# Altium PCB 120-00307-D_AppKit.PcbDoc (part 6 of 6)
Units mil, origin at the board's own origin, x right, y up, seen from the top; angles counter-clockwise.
Board outline 5150 x 3100 mil, 6 copper layers (L1, L2 (GND), L3-SIG, L4-SIG, L5 (PWR), L6), stack 61.956 mil thick; 413 components, 344 nets, 1685 pads, 1021 vias.
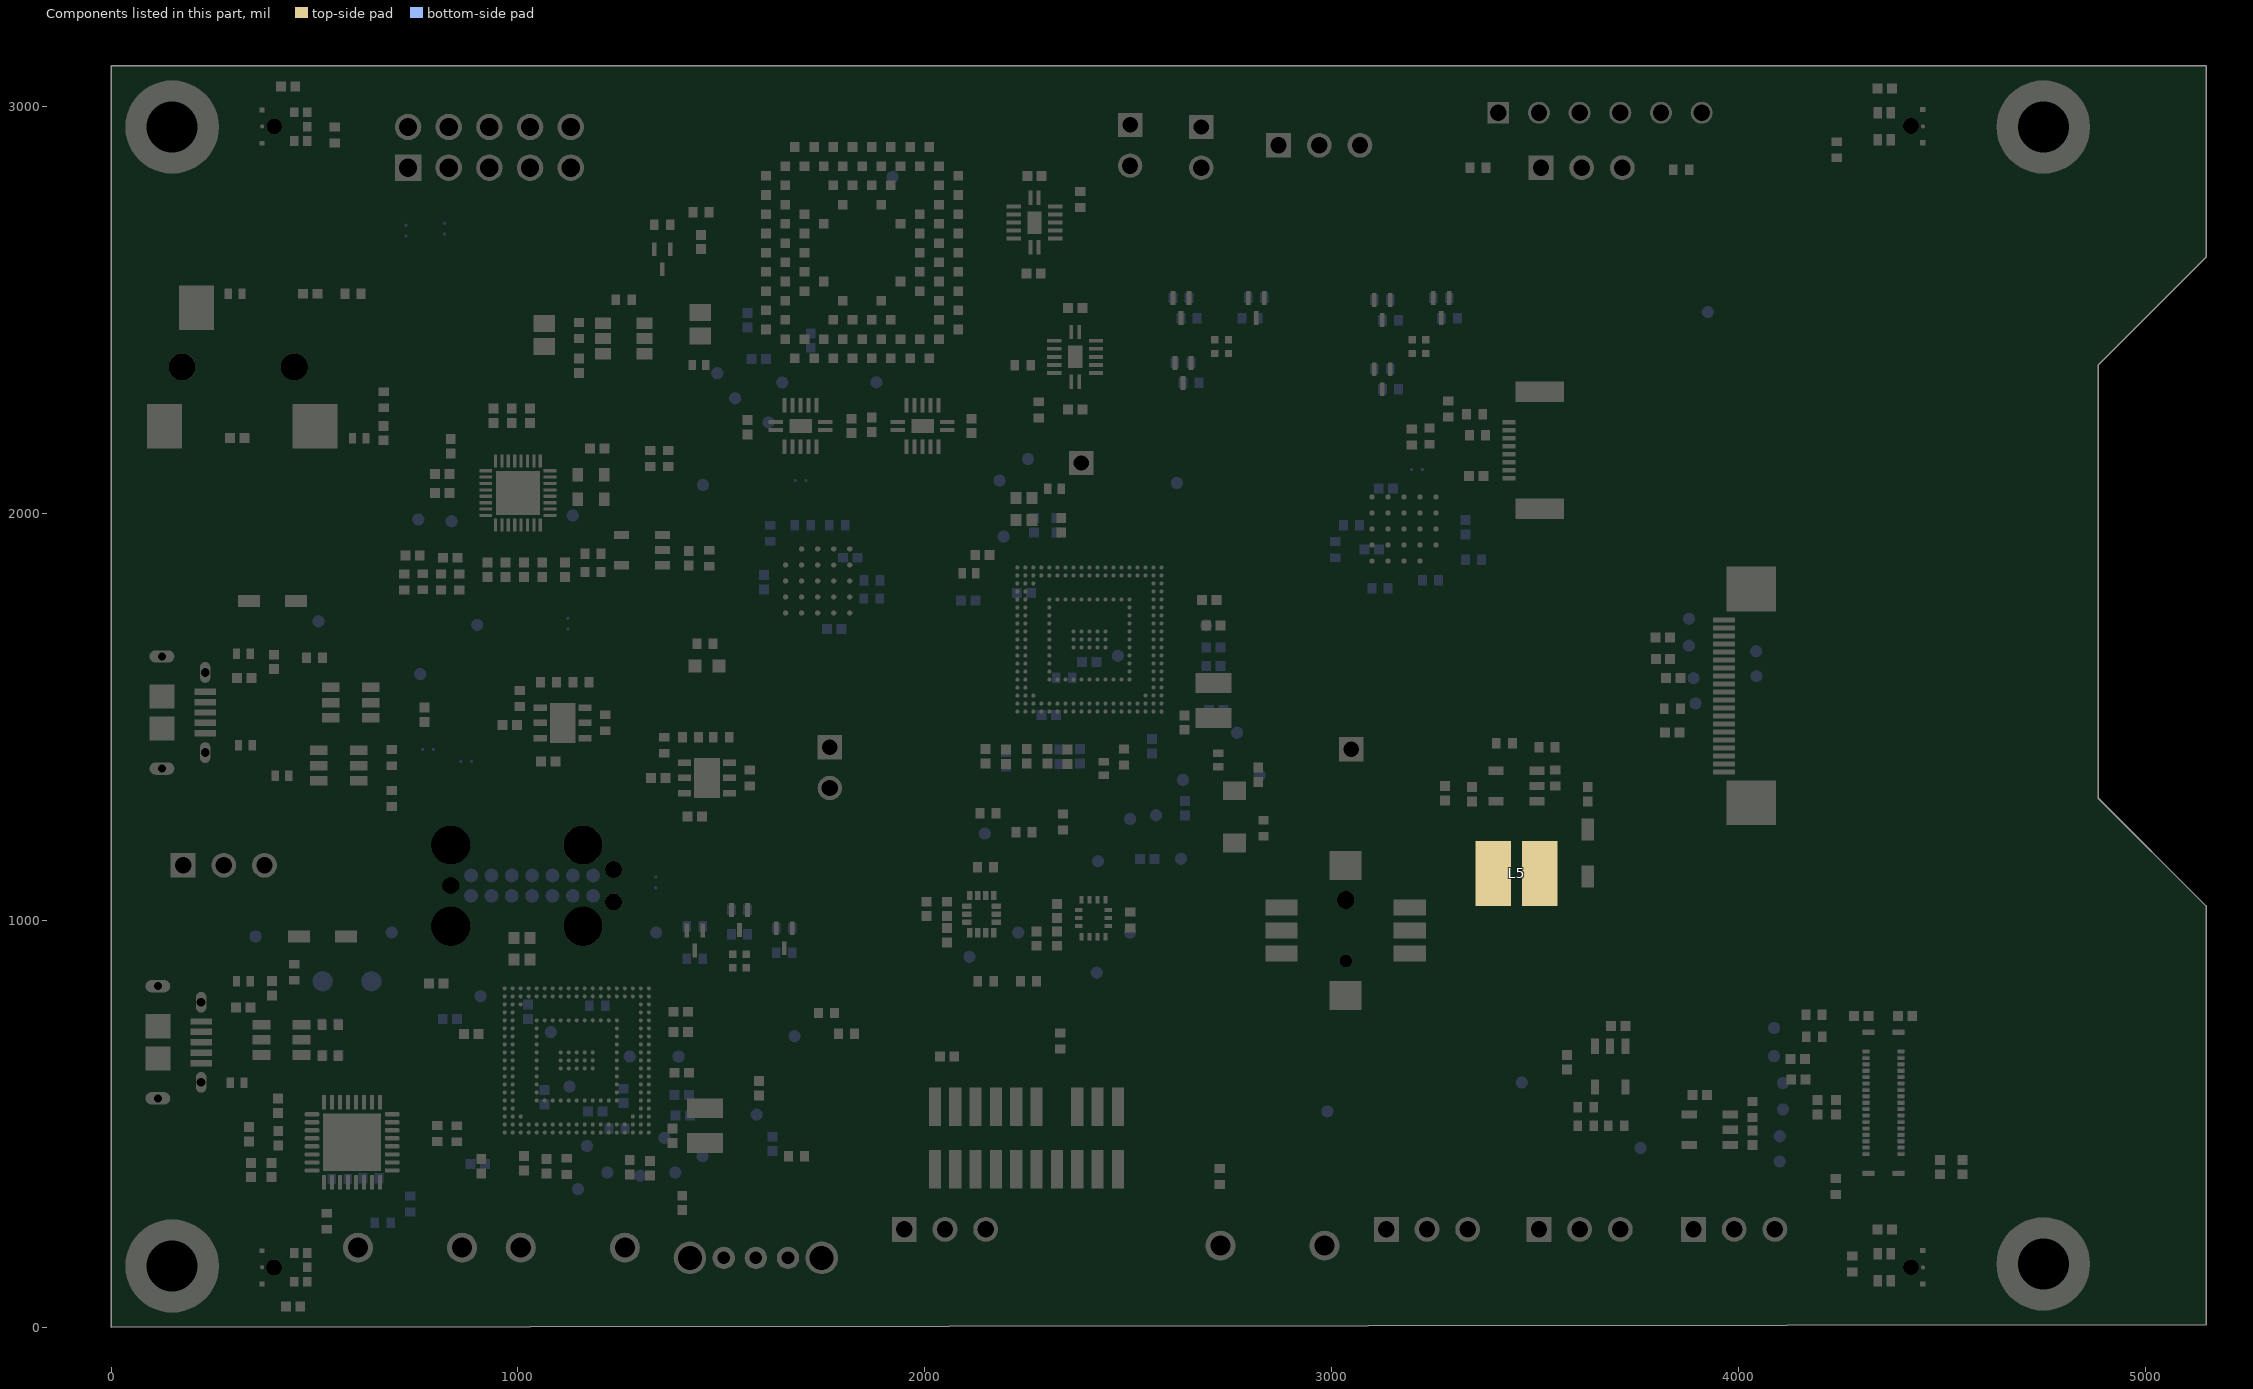
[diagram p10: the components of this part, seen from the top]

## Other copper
L1:
  pour cut-out: 990,810 1240,810 1250,800 1250,530 990,530
  pour cut-out: 1660,2850 1660,2440 2010,2440 2030,2420 2030,2840
  pour cut-out: 2240,1800 2240,1590 2440,1590 2450,1580 2450,1800
  pour cut-out: 346.77,199.99 346.77,85.33 456.77,85.33 456.77,200.33
  pour cut-out: 347.07,3004.42 347.07,2889.76 457.07,2889.76 457.07,3004.76
  pour cut-out: 4370,199.17 4370,93.68 4377.9,85.77 4480.36,85.77 4480.36,200.77
  pour cut-out: 4370.36,2890.76 4480.36,2890.76 4480.36,3005.76 4478.76,3004.16 4370,3004.16
  pour cut-out: 760,920 1300,920 1300,1260 760,1260
  region net GND: 3539,2324 3539,2368 3451,2368 3451,2324
  pour cut-out: 3490,1100 3656,1100 3664,1092 3653,1081 3653,1022 3491,1022 3490,1023
  pour cut-out: 3510,1358.4 3504,1352.4 3504,1107 3639,1107 3644,1112 3642,1114 3642,1359
  region net VDD_CORE_0V8: 2678,1490 2845,1490 2845,1400 2678,1400 2678,1414 2678,1450
  region net VDD_CORE_0V8_J: 1539,470 1539,385 1415,385 1399.68,400.32 1399.68,409.68 1399.68,470
  region net VIN_RAW: 3205,1305 3425,1305 3425,1030 3290,1030 3290,1190 3205,1190
L3-SIG:
  pour cut-out: 347.07,3004.42 347.07,2889.76 457.07,2889.76 457.07,3004.76
  pour cut-out: 346.77,199.99 346.77,85.33 456.77,85.33 456.77,200.33
  pour cut-out: 760,920 1300,920 1300,1260 760,1260
  pour cut-out: 4370.36,3005.42 4370.36,2890.76 4480.36,2890.76 4480.36,3005.76
  pour cut-out: 4370.36,200.43 4370.36,85.77 4480.36,85.77 4480.36,200.77
  pour cut-out: 346.77,199.99 346.77,85.33 456.77,85.33 456.77,200.33
  pour cut-out: 347.07,3004.42 347.07,2889.76 457.07,2889.76 457.07,3004.76
L4-SIG:
  pour cut-out: 760,920 1300,920 1300,1260 760,1260
  pour cut-out: 4370.36,3005.42 4370.36,2890.76 4480.36,2890.76 4480.36,3005.76
  pour cut-out: 4370.36,200.43 4370.36,85.77 4480.36,85.77 4480.36,200.77
  pour cut-out: 346.77,199.99 346.77,85.33 456.77,85.33 456.77,200.33
  pour cut-out: 347.07,3004.42 347.07,2889.76 457.07,2889.76 457.07,3004.76
L6:
  pour cut-out: 760,1260 760,920 1300,920 1300,1260
  pour cut-out: 4370.36,3005.42 4370.36,2890.76 4480.36,2890.76 4480.36,3005.76
  pour cut-out: 4370.36,200.43 4370.36,85.77 4480.36,85.77 4480.36,200.77
  pour cut-out: 346.77,199.99 346.77,85.33 456.77,85.33 456.77,200.33
  pour cut-out: 347.07,3004.42 347.07,2889.76 457.07,2889.76 457.07,3004.76
  region net VDD_CORE_0V8: 2835,1400 2835,1415 2811,1439 2703,1439 2703,1409 2712,1400
  text "'.PCB_DWG_NO'" at 3990,110 h50
  text "D" at 4552.24,59.12 h60
  text "R" at 4552.51,59.25 h60
L2 (GND) (plane layer: these items are gaps in the copper):
  region: 1330,3095 1330,2930 2355,2930 2355,3095
  lines w10: 1330,3095 1330,2930 2355,2930 2355,3105
  lines w20: 0,1790 0,1740 1210,1740 1210,1890 690,1890 ; 5,2620 690,2620 690,1895 ; 346.42,89.57 456.42,89.57 456.42,204.57 346.42,204.57 346.42,89.57 ; 346.71,2894.01 456.71,2894.01 456.71,3009.01 346.71,3009.01 346.71,2894.01 ; 4370,90.02 4480,90.02 4480,205.02 4370,205.02 4370,90.02 ; 4370,2895 4370,3010 4480,3010 4480,2895 4370,2895
L5 (PWR) (plane layer: these items are gaps in the copper):
  region: 2355,3100 2355,2930 1330,2930 1330,3095
  lines w10: 1330,3095 1330,2930 2355,2930 2355,3100
  lines w20: 346.42,204.24 346.42,89.57 456.42,89.57 456.42,204.57 351.42,204.57 ; 346.71,3008.67 346.71,2894.01 456.71,2894.01 456.71,3009.01 351.71,3009.01 ; 4370,204.68 4370,90.02 4480,90.02 4480,205.02 4375,205.02 ; 4370,3009.66 4370,2895 4480,2895 4480,3010 4375,3010 ; 980,1260 1230,1260 1230,1180 3280,1180 3280,360 4040,360 4055,360 4055,820 3510,820 3510,1380 2940,1380 2940,2290 3290,2290 3290,2430 2720,2430 2720,2360 2730,1380 2483,1380 1512,1380 1494.53,1397.47 1494.53,1750 1530,1750 1530,1910 980,1910 980,1340 980,1260

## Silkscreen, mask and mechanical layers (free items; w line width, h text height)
Top Overlay:
  drawing of 41 lines, arcs and shapes, not listed
  text "3V3" at 2445,3030 h80
  text "1V8" at 2620,3030 h80
  text "U4" at 1105,3020 h80
  text "SE" at 680.51,3018.83 h80
  text "U2" at 897,3017 h80
  text "1V8  3V3" at 2820,2975 h80
  text "SEMICONDUCTOR" at 5679,2856 h140
  text "HEADPHONES" at 50,2645 h120
  text "TP22" at 2445,2115 h30
  text "SOC USB" at 47,1885 h120
  text "'.ASSY_DWG_NO'" at 2787,1611 h50
  text "TP23" at 2995,1465 h30
  text "G T R" at 132,1205 h120
  text "U3V" at 1700,1190 h80
  text "ALIF" at 4286,1091 h300
  text "SEMICONDUCTOR" at 4285,992 h117
  text "www.alifsemi.com" at 3816,851 h60
  text "PRG USB" at 14,463 h75
  text "EN-DIS" at 1436,272 h120
  text "2V8  2V6" at 3850,70 h80
  text "G T R" at 3095,60 h120
  text "G T R" at 1910,55 h120
  text "A -- K" at 3475,50 h120
  text "RESET" at 2680,30 h120
Bottom Overlay:
  drawing of 27 lines, arcs and shapes, not listed
  text "'.PCB_DWG_NO'" at 3990,35 h50
Bottom Solder:
  text "D" at 4551.64,59.7 h60
  text "R" at 4551.91,59.84 h60
Drill Guide:
  the board outline again, w10
Mechanical 5:
  lines w2: 3431,2354 3571,2354 ; 3550,2155 4195,2155 ; 3940,1550 4300,1550
Drill Drawing:
  drawing of 197 lines, arcs and shapes, not listed
  text "Symbol" at 9917.08,6219.67 h72
  text "Count" at 10198.98,6219.67 h72
  text "Hole Size" at 10517.63,6219.67 h72
  text "Plated" at 11091.7,6219.67 h72
  text "Via/Pad" at 11339.17,6219.67 h72
  text "Hole Tolerance (+)" at 11634.39,6219.67 h72
  text "Hole Tolerance (-)" at 12236.7,6219.67 h72
  text "1" at 10198.98,6095.49 h60
  text "31.50mil (0.800mm)" at 10517.63,6095.49 h60
  text "NPTH" at 11091.7,6095.49 h60
  text "Pad" at 11339.17,6095.49 h60
  text "1" at 10198.98,5971.31 h60
  text "43.31mil (1.100mm)" at 10517.63,5971.31 h60
  text "NPTH" at 11091.7,5971.31 h60
  text "Pad" at 11339.17,5971.31 h60
  text "2" at 10198.98,5847.13 h60
  text "59.00mil (1.499mm)" at 10517.63,5847.13 h60
  text "PTH" at 11091.7,5847.13 h60
  text "Pad" at 11339.17,5847.13 h60
  text "2" at 10198.98,5722.95 h60
  text "66.93mil (1.700mm)" at 10517.63,5722.95 h60
  text "NPTH" at 11091.7,5722.95 h60
  text "Pad" at 11339.17,5722.95 h60
  text "3" at 10198.98,5598.77 h60
  text "31.00mil (0.787mm)" at 10517.63,5598.77 h60
  text "PTH" at 11091.7,5598.77 h60
  text "Pad" at 11339.17,5598.77 h60
  text "3" at 10198.98,5474.59 h60
  text "40.00mil (1.016mm)" at 10517.63,5474.59 h60
  text "PTH" at 11091.7,5474.59 h60
  text "Pad" at 11339.17,5474.59 h60
  text "3" at 10198.98,5350.41 h60
  text "42.00mil (1.067mm)" at 10517.63,5350.41 h60
  text "NPTH" at 11091.7,5350.41 h60
  text "Pad" at 11339.17,5350.41 h60
  text "A" at 9891.81,5340.41 h55.19
  text "4" at 10198.98,5226.22 h60
  text "19.69mil (0.500mm)" at 10517.63,5226.22 h60
  text "PTH" at 11091.7,5226.22 h60
  text "Pad" at 11339.17,5226.22 h60
  text "4" at 10198.98,5102.04 h60
  text "21.65mil (0.550mm)" at 10517.63,5102.04 h60
  text "PTH" at 11091.7,5102.04 h60
  text "Pad" at 11339.17,5102.04 h60
  text "4" at 10198.98,4977.86 h60
  text "39.00mil (0.991mm)" at 10517.63,4977.86 h60
  text "NPTH" at 11091.7,4977.86 h60
  text "Pad" at 11339.17,4977.86 h60
  text "4" at 10198.98,4853.68 h60
  text "96.50mil (2.451mm)" at 10517.63,4853.68 h60
  text "NPTH" at 11091.7,4853.68 h60
  text "Pad" at 11339.17,4853.68 h60
  text "4" at 10198.98,4729.5 h60
  text "125.00mil (3.175mm)" at 10517.63,4729.5 h60
  text "PTH" at 11091.7,4729.5 h60
  text "Pad" at 11339.17,4729.5 h60
  text "5" at 10198.98,4605.32 h60
  text "38.00mil (0.965mm)" at 10517.63,4605.32 h60
  text "PTH" at 11091.7,4605.32 h60
  text "Pad" at 11339.17,4605.32 h60
  text "6" at 10198.98,4481.14 h60
  text "49.21mil (1.250mm)" at 10517.63,4481.14 h60
  text "PTH" at 11091.7,4481.14 h60
  text "Pad" at 11339.17,4481.14 h60
  text "10" at 10198.98,4356.96 h60
  text "45.00mil (1.143mm)" at 10517.63,4356.96 h60
  text "PTH" at 11091.7,4356.96 h60
  text "Pad" at 11339.17,4356.96 h60
  text "27" at 10198.98,4232.78 h60
  text "40.16mil (1.020mm)" at 10517.63,4232.78 h60
  text "PTH" at 11091.7,4232.78 h60
  text "Pad" at 11339.17,4232.78 h60
  text "41" at 10198.98,4108.6 h60
  text "8.00mil (0.203mm)" at 10517.63,4108.6 h60
  text "PTH" at 11091.7,4108.6 h60
  text "Via" at 11339.17,4108.6 h60
  text "0.00mil (0.000mm)" at 11634.39,4108.6 h60
  text "8.00mil (0.203mm)" at 12236.7,4108.6 h60
  text "B" at 9891.81,4098.6 h55.19
  text "93" at 10198.98,3984.41 h60
  text "8.00mil (0.203mm)" at 10517.63,3984.41 h60
  text "PTH" at 11091.7,3984.41 h60
  text "Via" at 11339.17,3984.41 h60
  text "E" at 9891.81,3974.42 h55.19
  text "120" at 10198.98,3860.23 h60
  text "6.00mil (0.152mm)" at 10517.63,3860.23 h60
  text "PTH" at 11091.7,3860.23 h60
  text "Via" at 11339.17,3860.23 h60
  text "C" at 9891.81,3850.24 h55.19
  text "767" at 10198.98,3736.05 h60
  text "10.00mil (0.254mm)" at 10517.63,3736.05 h60
  text "PTH" at 11091.7,3736.05 h60
  text "Via" at 11339.17,3736.05 h60
  text "D" at 9891.81,3726.06 h55.19
  text "1104 Total" at 10198.98,3611.87 h60
  text "Slot definitions :" at 9917.08,3524.94 h60
  text "Routed Path Length" at 10326.29,3524.94 h60
  text "= Calculated from tool start centre position to tool end centre position." at 10833.25,3524.94 h60
  text "Hole Length" at 10326.29,3475.27 h60
  text "= Routed Path Length + Tool Size = Slot length as defined in the PCB layout" at 10645.04,3475.27 h60
  text "15" at -635,1900 h200
Assembly Notes:
  text "NOTES: (UNLESS OTHERWISE SPECIFIED)" at 451.88,13913.31 h125
  text "1. ASSEMBLE TO MEET INSPECTION CRITERIA OF" at 451.88,13601.31 h125
  text "IPC-A-610, CLASS 2, CURRENT REVISION." at 440.88,13369.31 h125
  text "2. BAG AND TAG (OR MARK CONTAINER) WITH PART NUMBER." at 440.88,13057.31 h125
  text "3. REFERENCE SCHEMATIC (OR AVL) FOR BILL OF MATERIALS." at 449.88,12649.31 h125
  text "4. ASSEMBLY SHOULD BE \"ROHS\" AND \"LEAD FREE\" COMPLIANT." at 468.21,12242.23 h125
Fab Notes:
  drawing of 406 lines, arcs and shapes, not listed
  text "NOTES: (UNLESS OTHERWISE SPECIFIED)" at -120.79,14743.23 h125
  text "THIS FAB SHOULD BE \"RoHS COMPLIANT\"." at -120.79,14543.23 h125
  text "1. FABRICATE TO IPC-A-600, CURRENT REVISION" at -279.79,14243.23 h125
  text "2. BOARD SHALL MEET THE INSPECTION CRITERIA OF" at -280.79,14043.23 h125
  text "a- ACCEPTABILITY AS PER IPC-A-600 (LATEST REVISION) CLASS II" at 99.21,13843.23 h125
  text "b- QUALIFICATION AND PERFORMANCE AS PER IPC-6012 (LATEST REVISION)  CLASS II." at -31.79,13652.23 h125
  text "3. MATERIAL: Isola_370HR (RoHS COMPLIANT MATERIAL) OR EQUIVALENT. GLASS" at -280.79,13418.23 h125
  text "TRANSITION TEMPERATURE MUST MEET OR EXCEED THE TEMPERATURE EXHIBITED" at 86.21,13243.23 h125
  text "WITH HIGH TEMPERATURE PROCESSES ASSOCIATED WITH LEAD FREE ASSEMBLY." at 98.21,13068.23 h125
  text "4. APPLY SOLDER MASK OVER BARE COPPER (SMOBC) IAW" at -280.79,12843.23 h125
  text "IPC-SM-840, BOTH SIDES, USING LPI, COLOR BLUE." at 80.21,12643.23 h125
  text "5. LPI SOLDER  MASK  TAIYO PSR4000 (RoHS COMPLIANT MATERIAL)  OR EQUIVALENT WILL BE  USED ON BOTH" at -280.79,12368.23 h125
  text "SIDES." at 87.21,12168.23 h125
  text "6. SOLDER MASK REQUIREMENTS FOR VIAS:" at -280.79,11918.23 h125
  text "a) ALL VIAS SHOWN IN DATA WITH SOLDER MASK RELIEF OF 6 MILS OVER VIA DRILL SIZE FROM BOTTOM SIDE, SHALL HAVE" at 80.21,11659.23 h125
  text "SOLDER MASK ENCROACHED (DRILL PLUS 6 MILS)." at 453.21,11484.23 h125
  text "b) ALL TENTED VIAS MUST BE PLUGED WITH SOLDERMASK." at 64.16,11189.07 h125
  text "7. SOLDER MASK REGISTRATION TO BE WITHIN DIAMETRICAL TRUE POSITION OF + / - 0.002\"WITH APPLICABLE" at -296.79,10727.23 h125
  text "HOLE / PAD." at 79.21,10552.23 h125
  text "8. FINISH: ENIG." at -296.79,10352.23 h125
  text "9. SILKSCREEN USING WHITE - HAVEN PC421 ( NON-CONDUCTIVE  OR EQUIVALENT  RoHS COMPLIANT MATERIAL)" at -296.79,10077.23 h125
  text "BOTH SIDES DISTORTION OF SILKSCREEN IS ACCEPTABLE  OVER TRACES.  EPOXY INK ON SOLDER LANDS IS" at 83.21,9902.23 h125
  text "NOT ACCEPTABLE." at 83.21,9727.23 h125
  text "10. VENDOR LOGO AND DATE CODE TO BE MARKED SOLDER  SIDE IN SILKSCREEN. MAXIMUM HEIGHT 0.12 INCHES." at -419.79,9502.23 h125
  text "11. 100% ELECTRICAL TEST REQUIRED FOR CONTINUITY. BOARD SHALL HAVE A" at -420.79,9302.23 h125
  text "UL-RATING OF 94V-0. UL SYMBOL AND RATING SHALL BE MARKED SOLDER SIDE IN SILKSCREEN." at 83.21,9127.23 h125
  text "12. REMOVE ALL UNUSED PADS FROM INTERNAL LAYERS." at -420.79,8902.23 h125
  text "13. 274X GERBER/ODB++ USED FOR FAB MUST BE VERIFIED AGAINST THE PROVIDED IPC356 NETLIST. COPPER" at -420.79,8652.23 h125
  text "SLIVERS THAT ARE LESS THAN 0.003\" IN WIDTH BETWEEN ANTI-PAD TO PLANE EDGE, ANTI-PAD TO SPLIT" at 76.21,8477.23 h125
  text "PLANE AND ANTI-PAD TO ANTI-PAD MUST BE REMOVED FROM THE MANUFACTURING ARTWORK. A NETLIST" at 80.21,8302.23 h125
  text "COMPARISON MUST BE PASSED WITH NO VIOLATION AFTER THE REMOVAL OF SLIVERS. ANY REQUIREMENT" at 87.21,8127.23 h125
  text "FOR SLIVER REMOVAL ABOVE OR EQUAL TO THE 0.003\" COPPER WIDTH MUST BE ADDRESSED AND APPROVED" at 79.21,7952.23 h125
  text "IN WRITING BY SUPPLIER." at 66.21,7777.23 h125
  text "14." at -380.84,7570.07 h125
  text "Finish:" at 58.16,7566.07 h125
  text "ENIG 3-8/180-220 microinches" at 864.16,7561.07 h125
  text "15. ALL 6 MIL VIA-IN-PAD ARE TO BE FILLED." at -394,7217 h200
  text "90 OHM DIFFERENTIAL PAIRS" at 3201.93,6501.23 h125
  text "100 OHM DIFFERENTIAL PAIRS" at -400,6500 h125
  text "100 ohm diff pairs:" at 6937.1,6444.4 h125
  text "MIPI_CSI_0_N" at -400,6200 h125
  text "Inner Layers:" at 6900,6175 h125
  text "USB_CYP_N" at 3190.6,6154 h125
  text "MIPI_CSI_0_P" at -400,6000 h125
  text "USB_CYP_P" at 3190.6,5954 h125
  text "4.2mil Trace/10mil space" at 6919.33,5948.2 h125
  text "MIPI_CSI_1_N" at -400,5800 h125
  text "USB_DEV_N" at 3190.6,5754 h125
  text "Outer Layers:" at 6879.48,5687.68 h125
  text "MIPI_CSI_1_P" at -400,5600 h125
  text "USB_DEV_P" at 3190.6,5554 h125
  text "3.2 Trace/3.8 Space" at 6879.48,5462.68 h125
  text "MIPI_CSI_C_N" at -400,5400 h125
  text "USB_D_N" at 3190.6,5354 h125
  text "MIPI_CSI_C_P" at -400,5200 h125
  text "USB_D_P" at 3190.6,5154 h125
  text "90 ohm diff pairs:" at 6837.5,5028.2 h125
  text "MIPI_DSI_0_N" at -398.08,4996.6 h125
  text "USB_FTDI_N" at 3190.6,4954 h125
  text "MIPI_DSI_0_P" at -398.08,4796.6 h125
  text "Inner Layers:" at 6800.4,4758.8 h125
  text "USB_FTDI_P" at 3190.6,4754 h125
  text "MIPI_DSI_1_N" at -398.08,4596.6 h125
  text "USB_U_N" at 3190.6,4554 h125
  text "11mil Trace/4mil space" at 6819.73,4532 h125
  text "MIPI_DSI_1_P" at -398.08,4396.6 h125
  text "USB_U_P" at 3190.6,4354 h125
  text "Outer Layers:" at 6779.88,4271.48 h125
  text "MIPI_DSI_C_N" at -398.08,4196.6 h125
  text "3mil Trace/5mil Space" at 6779.88,4046.48 h125
  text "MIPI_DSI_C_P" at -398.08,3996.6 h125
  text "Layer" at 7170.34,3130 h60
  text "Name" at 7580.26,3130 h60
  text "Material" at 8510,3130 h60
  text "Thickness" at 9109.85,3130 h60
  text "Constant" at 9759.69,3130 h60
  text "Board Layer Stack" at 10329.55,3130 h60
  text "Top Overlay" at 7580.26,3010 h60
  text "Top Solder" at 7580.26,2890 h60
  text "SM-001" at 8510,2890 h60
  text "0.70mil" at 9109.85,2890 h60
  text "4" at 9759.69,2890 h60
  text "1" at 7170.34,2770 h60
  text "L1" at 7580.26,2770 h60
  text "CF-003" at 8510,2770 h60
  text "1.38mil" at 9109.85,2770 h60
  text "Dielectric 1" at 7580.26,2650 h60
  text "PP-008" at 8510,2650 h60
  text "3.10mil" at 9109.85,2650 h60
  text "4.1" at 9759.69,2650 h60
  text "2" at 7170.34,2530 h60
  text "L2 (GND)" at 7580.26,2530 h60
  text "CF-003" at 8510,2530 h60
  text "0.60mil" at 9109.85,2530 h60
  text "Dielectric 3" at 7580.26,2410 h60
  text "Core-035" at 8510,2410 h60
  text "4.51mil" at 9109.85,2410 h60
  text "4.7" at 9759.69,2410 h60
  text "3" at 7170.34,2290 h60
  text "L3-SIG" at 7580.26,2290 h60
  text "CF-003" at 8510,2290 h60
  text "0.60mil" at 9109.85,2290 h60
  text "Dielectric 2" at 7580.26,2170 h60
  text "PP-006" at 8510,2170 h60
  text "41.58mil" at 9109.85,2170 h60
  text "4.1" at 9759.69,2170 h60
  text "4" at 7170.34,2050 h60
  text "L4-SIG" at 7580.26,2050 h60
  text "CF-003" at 8510,2050 h60
  text "0.60mil" at 9109.85,2050 h60
  text "Dielectric 6" at 7580.26,1930 h60
  text "Core-035" at 8510,1930 h60
  text "4.51mil" at 9109.85,1930 h60
  text "4.7" at 9759.69,1930 h60
  text "5" at 7170.34,1810 h60
  text "L5 (PWR)" at 7580.26,1810 h60
  text "CF-003" at 8510,1810 h60
  text "0.60mil" at 9109.85,1810 h60
  text "Dielectric 8" at 7580.26,1690 h60
  text "PP-008" at 8510,1690 h60
  text "3.10mil" at 9109.85,1690 h60
  text "4.1" at 9759.69,1690 h60
  text "6" at 7170.34,1570 h60
  text "L6" at 7580.26,1570 h60
  text "CF-003" at 8510,1570 h60
  text "1.38mil" at 9109.85,1570 h60
  text "Bottom Solder" at 7580.26,1450 h60
  text "SM-001" at 8510,1450 h60
  text "0.70mil" at 9109.85,1450 h60
  text "4" at 9759.69,1450 h60
  text "Bottom Overlay" at 7580.26,1330 h60
  text "Total board thickness:" at 7170.34,1210 h60
  text "63.36mil" at 9109.85,1210 h60

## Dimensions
150,2950 to 4750,2950 on Mechanical 1
0,0 to 5150,3100 on Drill Drawing
5150,2630 to 5150,5 on Drill Drawing
3979.5,1770 to 4900,2285 on Mechanical 1
4900,2065 to 4129.5,2780 on Mechanical 1
3550,2155 to -20.5,320 on Mechanical 1
4300,1550 to 4129.5,320 on Mechanical 1
4940,5 to 4750,155 on Drill Drawing
5150,5 to 4750,155 on Drill Drawing
4320,3100 to 4750,2950 on Drill Drawing
4750,2950 to 0,3100 on Drill Drawing
-20.5,2780 to 4129.5,2780 on Drill Drawing
0,3105 to 150,2950 on Drill Drawing
-20.5,320 to 150,150 on Drill Drawing
5150,2630 to 150,2950 on Drill Drawing
0,0 to 5150,2630 on Drill Drawing
150,150 to 150,2950 on Mechanical 1
-20.5,320 to -20.5,2780 on Drill Drawing
0,0 to 150,150 on Drill Drawing
150,2950 to -20.5,2780 on Drill Drawing
-20.5,320 to 150,150 on Drill Drawing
